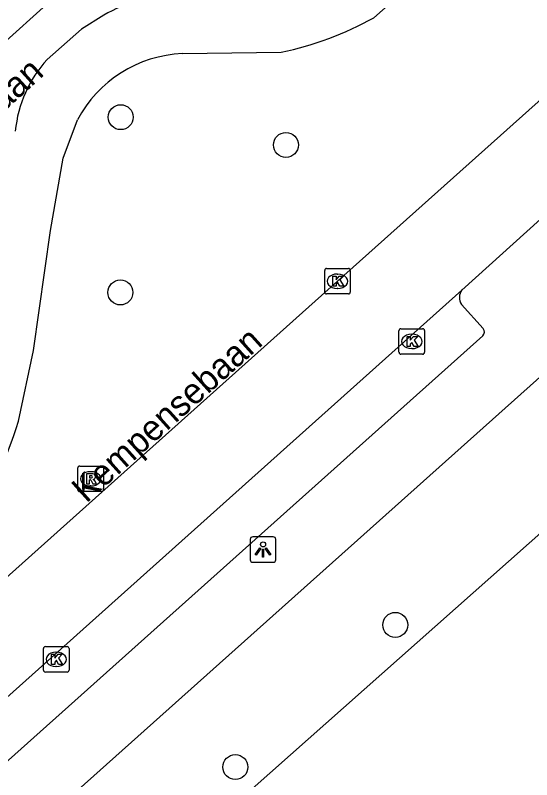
# Model space of a CAD drawing. Extents: x 162172 to 163187, y 382874 to 383684.
# Drawn here: x 162635.94 to 162656.16, y 383205.06 to 383235.01 of the extents above; entities that cross this region are included whole.
import ezdxf

# ---------------------------------------------------------------- set-up
doc = ezdxf.new("R2010")
doc.units = 0
for name, color, linetype in [('IMGEO_Boom', 7, 'Continuous'), ('IMGEO_Groenvoorziening', 7, 'Continuous'), ('IMGEO_Hek', 7, 'Continuous'), ('IMGEO_Kolk', 7, 'Continuous'), ('IMGEO_Lichtpunt', 7, 'Continuous'), ('IMGEO_Openbare_ruimte_label', 7, 'Continuous'), ('IMGEO_Rijbaan_lokaal_open', 7, 'Continuous'), ('IMGEO_Rioolput', 7, 'Continuous'), ('IMGEO_Voetpad_gesloten', 7, 'Continuous'), ('IMGEO_Voetpad_open', 7, 'Continuous')]:
    doc.layers.add(name, color=color, linetype=linetype)

msp = doc.modelspace()

# ---------------------------------------------------------------- linework, layer by layer
at = {"layer": 'IMGEO_Boom'}
for centre in [(162640.07, 383231.022), (162646.541, 383229.935), (162640.058, 383224.153), (162650.822, 383211.129), (162644.559, 383205.558)]:
    msp.add_circle(centre, 0.489, dxfattribs=at)
at = {"layer": 'IMGEO_Groenvoorziening'}
msp.add_lwpolyline([(162712.311, 383195.573), (162709.753, 383226.486), (162692.642, 383246.796), (162622.24, 383184.334), (162683.702, 383170.501), (162683.655, 383170.289)], dxfattribs=at)
at = {"layer": 'IMGEO_Hek'}
msp.add_lwpolyline([(162683.702, 383170.501), (162622.24, 383184.334), (162692.642, 383246.796), (162709.753, 383226.486), (162712.533, 383192.884)], dxfattribs=at)
at = {"layer": 'IMGEO_Kolk'}
for p, q in [((162648.057, 383224.168), (162648.057, 383225.02)), ((162648.132, 383225.094), (162648.984, 383225.094)), ((162648.545, 383224.874), (162648.57, 383224.874)), ((162649.058, 383225.02), (162649.058, 383224.168)), ((162648.568, 383224.314), (162648.543, 383224.314)), ((162648.984, 383224.094), (162648.132, 383224.094)), ((162651.042, 383222.734), (162651.894, 383222.734)), ((162650.967, 383221.808), (162650.967, 383222.66)), ((162651.455, 383222.514), (162651.48, 383222.514)), ((162651.968, 383222.66), (162651.968, 383221.808)), ((162651.478, 383221.954), (162651.453, 383221.954)), ((162651.894, 383221.734), (162651.042, 383221.734)), ((162637.046, 383209.351), (162637.046, 383210.203)), ((162637.121, 383210.277), (162637.973, 383210.277)), ((162638.047, 383210.203), (162638.047, 383209.351)), ((162637.534, 383210.057), (162637.559, 383210.057)), ((162637.973, 383209.277), (162637.121, 383209.277)), ((162637.557, 383209.497), (162637.532, 383209.497))]:
    msp.add_line(p, q, dxfattribs=at)
for points in [[(162648.057, 383224.168), (162648.057, 383225.02)], [(162648.132, 383225.094), (162648.984, 383225.094)], [(162649.058, 383225.02), (162649.058, 383224.168)], [(162648.378, 383224.794), (162648.501, 383224.794), (162648.501, 383224.643), (162648.631, 383224.794), (162648.795, 383224.794), (162648.649, 383224.643), (162648.802, 383224.394), (162648.65, 383224.394), (162648.565, 383224.558), (162648.501, 383224.491), (162648.501, 383224.394), (162648.378, 383224.394), (162648.378, 383224.794)], [(162648.984, 383224.094), (162648.132, 383224.094)], [(162651.042, 383222.734), (162651.894, 383222.734)], [(162650.967, 383221.808), (162650.967, 383222.66)], [(162651.288, 383222.434), (162651.411, 383222.434), (162651.411, 383222.283), (162651.541, 383222.434), (162651.705, 383222.434), (162651.559, 383222.283), (162651.712, 383222.034), (162651.56, 383222.034), (162651.475, 383222.198), (162651.411, 383222.131), (162651.411, 383222.034), (162651.288, 383222.034), (162651.288, 383222.434)], [(162651.968, 383222.66), (162651.968, 383221.808)], [(162651.894, 383221.734), (162651.042, 383221.734)], [(162637.046, 383209.351), (162637.046, 383210.203)], [(162637.121, 383210.277), (162637.973, 383210.277)], [(162638.047, 383210.203), (162638.047, 383209.351)], [(162637.367, 383209.977), (162637.49, 383209.977), (162637.49, 383209.826), (162637.62, 383209.977), (162637.784, 383209.977), (162637.638, 383209.826), (162637.791, 383209.577), (162637.639, 383209.577), (162637.554, 383209.741), (162637.49, 383209.674), (162637.49, 383209.577), (162637.367, 383209.577), (162637.367, 383209.977)], [(162637.973, 383209.277), (162637.121, 383209.277)]]:
    msp.add_lwpolyline(points, dxfattribs=at)
for centre, start, end in [((162648.134, 383225.018), 91.552, 178.448), ((162648.134, 383225.018), 91.552, 178.448), ((162648.982, 383225.018), 1.552, 88.448), ((162648.982, 383225.018), 1.552, 88.448), ((162648.134, 383224.17), 181.552, 268.448), ((162648.134, 383224.17), 181.552, 268.448), ((162648.982, 383224.17), 271.552, 358.448), ((162648.982, 383224.17), 271.552, 358.448), ((162651.044, 383222.658), 91.552, 178.448), ((162651.044, 383222.658), 91.552, 178.448), ((162651.892, 383222.658), 1.552, 88.448), ((162651.892, 383222.658), 1.552, 88.448), ((162651.044, 383221.81), 181.552, 268.448), ((162651.044, 383221.81), 181.552, 268.448), ((162651.892, 383221.81), 271.552, 358.448), ((162651.892, 383221.81), 271.552, 358.448), ((162637.123, 383210.201), 91.552, 178.448), ((162637.123, 383210.201), 91.552, 178.448), ((162637.971, 383210.201), 1.552, 88.448), ((162637.971, 383210.201), 1.552, 88.448), ((162637.123, 383209.353), 181.552, 268.448), ((162637.123, 383209.353), 181.552, 268.448), ((162637.971, 383209.353), 271.552, 358.448), ((162637.971, 383209.353), 271.552, 358.448)]:
    msp.add_arc(centre, 0.0765, start, end, dxfattribs=at)
for centre, major_axis, ratio, start_param, end_param in [((162648.544, 383224.594), (-0.387, 0.002), 0.722429, 4.712389, 7.853982), ((162648.569, 383224.594), (-0.39, 0.002), 0.717154, 1.570796, 4.712389), ((162651.454, 383222.234), (-0.387, 0.002), 0.722429, 4.712389, 7.853982), ((162651.479, 383222.234), (-0.39, 0.002), 0.717154, 1.570796, 4.712389), ((162637.533, 383209.777), (-0.387, 0.002), 0.722429, 4.712389, 7.853982), ((162637.558, 383209.777), (-0.39, 0.002), 0.717154, 1.570796, 4.712389)]:
    msp.add_ellipse(centre, major_axis=major_axis, ratio=ratio, start_param=start_param, end_param=end_param, dxfattribs=at)
at = {"layer": 'IMGEO_Lichtpunt'}
for p, q in [((162645.144, 383214.482), (162645.144, 383213.675)), ((162645.144, 383214.482), (162645.144, 383213.675)), ((162646.046, 383214.577), (162645.238, 383214.577)), ((162646.046, 383214.577), (162645.238, 383214.577)), ((162646.14, 383213.675), (162646.14, 383214.482)), ((162646.14, 383213.675), (162646.14, 383214.482)), ((162645.238, 383213.581), (162646.046, 383213.581)), ((162645.238, 383213.581), (162646.046, 383213.581))]:
    msp.add_line(p, q, dxfattribs=at)
for points in [[(162645.518, 383214.146), (162645.557, 383214.118), (162645.369, 383213.856), (162645.331, 383213.883), (162645.518, 383214.146)], [(162645.62, 383214.098), (162645.667, 383214.098), (162645.667, 383213.776), (162645.62, 383213.776), (162645.62, 383214.098)], [(162645.73, 383214.118), (162645.768, 383214.145), (162645.955, 383213.883), (162645.916, 383213.855), (162645.73, 383214.118)]]:
    msp.add_lwpolyline(points, dxfattribs=at)
msp.add_circle((162645.643, 383214.28), 0.0994, dxfattribs=at)
for centre, start, end in [((162645.238, 383214.482), 90, 180), ((162645.238, 383214.482), 90, 180), ((162646.046, 383214.482), 0, 90), ((162646.046, 383214.482), 0, 90), ((162645.238, 383213.675), 180, 270), ((162645.238, 383213.675), 180, 270), ((162646.046, 383213.675), 270, 0), ((162646.046, 383213.675), 270, 360)]:
    msp.add_arc(centre, 0.0946, start, end, dxfattribs=at)
at = {"layer": 'IMGEO_Rijbaan_lokaal_open'}
for points in [[(162594.538, 383197.307), (162598.429, 383200.785), (162614.417, 383215.084), (162631.839, 383230.648), (162640.771, 383238.704), (162646.358, 383243.687), (162663.821, 383259.29), (162676.816, 383270.908), (162691.32, 383283.864), (162708.036, 383298.826), (162711.785, 383302.188)], [(162694.039, 383265.267), (162682.786, 383255.183), (162664.524, 383238.887), (162648.558, 383224.594), (162634.825, 383212.308), (162621.087, 383200.028), (162606.584, 383187.068), (162604.928, 383185.572)], [(162653.433, 383224.25), (162656.506, 383227.023)], [(162617.125, 383191.769), (162633.608, 383206.492), (162653.433, 383224.25)]]:
    msp.add_lwpolyline(points, dxfattribs=at)
at = {"layer": 'IMGEO_Rioolput'}
for p, q in [((162638.466, 383217.352), (162639.318, 383217.352)), ((162638.391, 383216.426), (162638.391, 383217.278)), ((162638.879, 383217.132), (162638.904, 383217.132)), ((162639.392, 383217.278), (162639.392, 383216.426)), ((162638.902, 383216.572), (162638.877, 383216.572)), ((162639.318, 383216.352), (162638.466, 383216.352))]:
    msp.add_line(p, q, dxfattribs=at)
for points in [[(162638.466, 383217.352), (162639.318, 383217.352)], [(162638.391, 383216.426), (162638.391, 383217.278)], [(162638.98, 383217.05), (162638.728, 383217.052), (162638.728, 383216.652)], [(162639.392, 383217.278), (162639.392, 383216.426)], [(162638.728, 383216.652), (162638.852, 383216.652), (162638.852, 383216.814), (162638.863, 383216.814)], [(162638.906, 383216.971), (162638.852, 383216.971), (162638.852, 383216.89)], [(162638.852, 383216.89), (162638.904, 383216.89)], [(162638.91, 383216.785), (162638.981, 383216.652), (162639.121, 383216.652), (162639.056, 383216.778)], [(162639.318, 383216.352), (162638.466, 383216.352)]]:
    msp.add_lwpolyline(points, dxfattribs=at)
for centre, radius, start, end in [((162638.468, 383217.276), 0.0765, 91.552, 178.448), ((162638.468, 383217.276), 0.0765, 91.552, 178.448), ((162639.316, 383217.276), 0.0765, 1.552, 88.448), ((162639.316, 383217.276), 0.0765, 1.552, 88.448), ((162638.979, 383216.94), 0.109, 350.3612, 89.416), ((162638.862, 383216.761), 0.0533, 26.0293, 88.6989), ((162638.888, 383217.079), 0.19, 274.7715, 282.9687), ((162638.912, 383216.875), 0.0964, 77.0061, 93.1865), ((162638.926, 383216.932), 0.0378, 276.6634, 79.6772), ((162638.977, 383216.94), 0.112, 277.5842, 350.9817), ((162638.961, 383216.725), 0.108, 29.5134, 73.7905), ((162638.468, 383216.428), 0.0765, 181.552, 268.448), ((162638.468, 383216.428), 0.0765, 181.552, 268.448), ((162639.316, 383216.428), 0.0765, 271.552, 358.448), ((162639.316, 383216.428), 0.0765, 271.552, 358.448)]:
    msp.add_arc(centre, radius, start, end, dxfattribs=at)
for centre, major_axis, ratio, start_param, end_param in [((162638.878, 383216.852), (-0.387, 0.002), 0.722429, 4.712389, 7.853982), ((162638.903, 383216.852), (-0.39, 0.002), 0.717154, 1.570796, 4.712389)]:
    msp.add_ellipse(centre, major_axis=major_axis, ratio=ratio, start_param=start_param, end_param=end_param, dxfattribs=at)
at = {"layer": 'IMGEO_Voetpad_gesloten'}
for points in [[(162649.984, 383234.92), (162662.446, 383245.946)], [(162639.411, 383235.014), (162638.529, 383234.47), (162637.19, 383233.282)], [(162642.489, 383233.511), (162646.359, 383233.567)], [(162636.071, 383219.114), (162636.659, 383221.876), (162637.32, 383226.588), (162637.817, 383229.42), (162638.374, 383230.912)]]:
    msp.add_lwpolyline(points, dxfattribs=at)
for centre, radius, start, end in [((162642.538, 383229.699), 6.167, 93.0202, 120.4683), ((162643.668, 383246.31), 13.024, 281.925, 299.0103), ((162642.693, 383228.63), 4.885, 92.3988, 152.1536), ((162640.815, 383229.991), 4.897, 137.7646, 174.2991), ((162619.346, 383224.234), 17.491, 311.7488, 342.9775)]:
    msp.add_arc(centre, radius, start, end, dxfattribs=at)
at = {"layer": 'IMGEO_Voetpad_open'}
for points in [[(162689.625, 383250.21), (162689.305, 383250), (162664.293, 383227.801), (162660.781, 383224.678), (162625.12, 383192.791)], [(162654.262, 383222.736), (162653.41, 383223.685)], [(162618.813, 383190.745), (162634.926, 383205.165), (162654.249, 383222.454)]]:
    msp.add_lwpolyline(points, dxfattribs=at)
for centre, radius, start, end in [((162653.835, 383223.951), 0.501, 143.3274, 212.0103), ((162654.1, 383222.602), 0.21, 315.2507, 39.4705)]:
    msp.add_arc(centre, radius, start, end, dxfattribs=at)

# ---------------------------------------------------------------- texts
at = {"layer": 'IMGEO_Openbare_ruimte_label'}
for rotation, p in [(42.0809, (162630.163, 383226.415)), (41.9617, (162638.721, 383215.873))]:
    msp.add_text('Kempensebaan', height=1, rotation=rotation, dxfattribs=at).set_placement(p)

doc.saveas('drawing.dxf')
